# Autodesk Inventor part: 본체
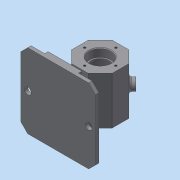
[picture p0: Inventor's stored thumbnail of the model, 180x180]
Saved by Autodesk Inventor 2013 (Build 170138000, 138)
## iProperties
Created: 2018-06
Part Number: 본체
Material: 일반
Document SubType Name: Modeling
Designer: Administrator
Density: 1 g/cm^3
Author: Administrator
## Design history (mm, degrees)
sketch "스케치1" dims "d0" = 60
  geometry: L1 (30, 12.426)-(30, -12.426); L2 (30, -12.426)-(12.426, -30); L3 (12.426, -30)-(-12.426, -30); L4 (-12.426, -30)-(-30, -12.426); L5 (-30, -12.426)-(-30, 12.426); L6 (-30, 12.426)-(-12.426, 30); L7 (-12.426, 30)-(12.426, 30); L8 (12.426, 30)-(30, 12.426); L9 (55, -57)-(55, -62); L10 (55, -62)-(-55, -62); L11 (-55, -62)-(-55, -57); L12 (-25, -52)-(25, -52); L13 (25, -52)-(25, -57); L14 (-25, -57)-(-25, -52); L15 (-55, -57)-(25, -57); L16 (25, -57)-(55, -57); 7 further points
  constraints: 32 end point, 4 midpoint, 4 parallel, 3 horizontal, 3 perpendicular, 3 vertical alignment, 2 coincident, 1 collinear, 1 point on line, 20 other
  dimensions: "d3" = 5 distance of L10.end L11.end; "d4" = 10 distance between parallel lines of L10 L12; "d5" = 110 distance of L9.end L10.end; "d6" = 62 distance from line of point (0, 0) L10; "d7" = 50 distance of L12.start L12.end
extrude "돌출1" new body sketch "스케치1" distance "d1" = 35; taper "d2" = 0 deg
extrude "돌출2" join sketch "스케치1" distance "d8" = 55; taper "d9" = 0 deg
extrude "돌출3" join sketch "스케치1" distance "d10" = 55; taper "d11" = 0 deg
chamfer "모따기1" distance "d13" = 10; stored, may be unused: second distance "d14" = 2, angle "d15" = 45 deg
sketch "스케치2"
  geometry: 2 further points
  constraints: 1 coincident
hole "구멍1" sketch "스케치2" at (0, 0) diameter "d18" = 28; stored, may be unused: countersink angle "d22" = 90 deg, drill point angle "d24" = 0 deg; dims "d19" = 6, "d20" = 32, "d21" = 12, "d23" = 15
sketch "스케치4"
  geometry: C1 r 25 at (0, 0); 1 further point
  constraints: 1 centre point, 1 coincident
  dimensions: "d40" = 50 diameter of C1
extrude "돌출4" cut sketch "스케치4" distance "d41" = 20; taper "d42" = 0 deg
sketch "스케치3"
  geometry: C1 r 16 at (0, 0) reference; 1 further point
  constraints: 1 vertical alignment
  dimensions: "d25" = 23 distance of C1.centre point (0, 23)
hole "구멍2" sketch "스케치3" at (0, 23) diameter "d26" = 3.242; stored, may be unused: countersink angle "d30" = 90 deg, drill point angle "d32" = 118 deg; dims "d27" = 8, "d28" = 32, "d29" = 12, "d31" = 10
chamfer "모따기2" distance "d36" = 1; stored, may be unused: second distance "d37" = 2, angle "d38" = 45 deg
fillet "모깎기2" dims "d39" = 0.3, "d43" = 3
sketch "스케치5"
  geometry: L1 (25, 31)-(25, 31); L2 (30, 36)-(30, 74); L3 (25, 79)-(25, 79); L4 (20, 74)-(20, 36); A1 r 5 centre (25, 74) between (25, 79) and (20, 74); A2 r 5 centre (25, 74) between (30, 74) and (25, 79); A3 r 5 centre (25, 36) between (20, 36) and (25, 31); A4 r 5 centre (25, 36) between (25, 31) and (30, 36); 6 further points
  constraints: 8 end point, 8 point on circle, 8 tangent, 6 point on line, 4 centre point, 3 equal radius, 2 midpoint, 2 parallel, 1 horizontal, 1 horizontal alignment, 1 perpendicular, 1 vertical alignment
  dimensions: "d44" = 48 distance of point (20, 79) point (20, 31); "d46" = 10 distance of point (30, 79) point (20, 79); "d47" = 5 radius of A1
extrude "돌출5" join sketch "스케치5" stored distance "d48" = 20; taper "d49" = 0 deg
fillet "모깎기3" dims "d50" = 2
sketch "스케치6"
  geometry: L1 (30, 100)-(30, 10) reference; C1 r 5 at (20, 55); 1 further point
  constraints: 1 centre point, 1 horizontal alignment
  dimensions: "d51" = 10 diameter of C1; "d52" = 10 distance from line of L1 C1.centre
extrude "돌출6" cut sketch "스케치6" stored distance "d53" = 20; taper "d54" = 0 deg
fillet "모깎기4" dims "d55" = 1
sketch "스케치7"
  geometry: C1 r 8 at (12.012, 35); 1 further point
  constraints: 1 centre point, 1 coincident
  dimensions: "d56" = 16 diameter of C1
extrude "돌출7" join sketch "스케치7" distance "d57" = 7; taper "d58" = 0 deg
hole "구멍3" diameter "d61" = 8; stored, may be unused: countersink angle "d65" = 90 deg, drill point angle "d67" = 0 deg; dims "d59" = 10, "d60" = 10, "d62" = 8, "d63" = 32, "d64" = 12, "d66" = 10
fillet "모깎기5" dims "d68" = 3
chamfer "모따기3" distance "d69" = 1; stored, may be unused: second distance "d70" = 2, angle "d71" = 45 deg
sketch "스케치8"
  geometry: L1 (24.024, -70)-(0, -70) reference; L2 (-17.988, 0)-(-17.988, -70) reference; 2 further points
  constraints: 1 other
  dimensions: "d72" = 35 distance from line of point (12.012, -35) L1; "d73" = 30 distance from line of point (12.012, -35) L2
feature "엠보싱1" sketch "스케치8" dims "d74" = 0.5, "d75" = 0
node "솔리드1"
pattern_circular "원형 패턴1" dims angle "d34" = 360 deg
mirror "대칭1"
mirror "대칭2"
